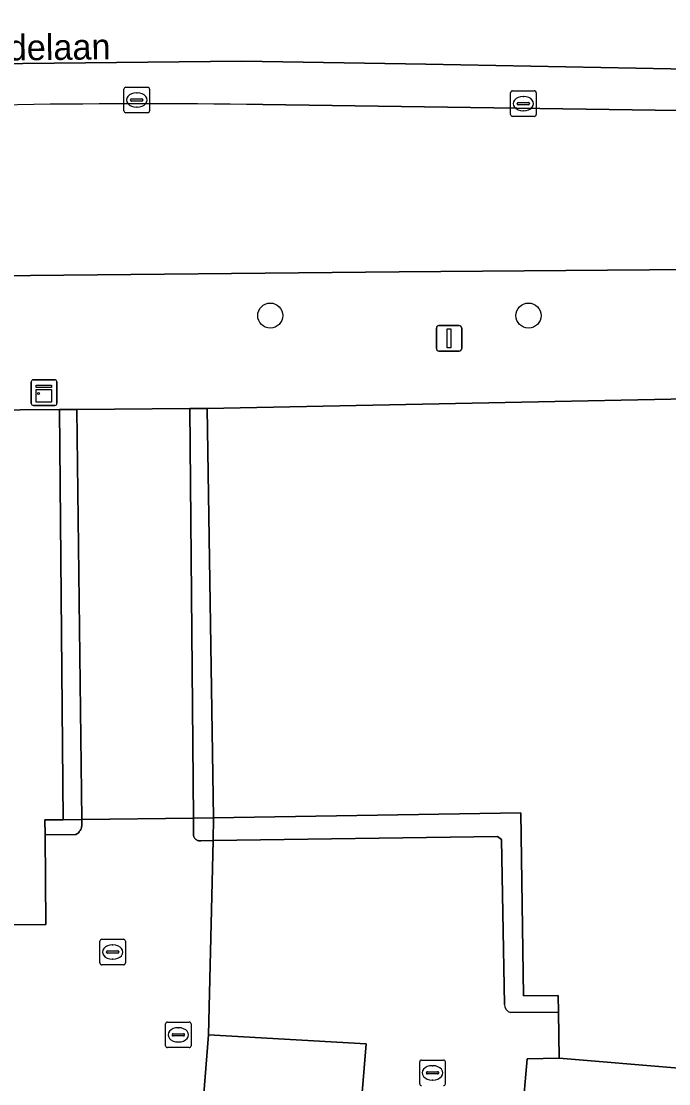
# Model space of a CAD drawing. Extents: x 160856 to 161310, y 384024 to 384878.
# Drawn here: x 161171.62 to 161196.94, y 384253.51 to 384295.05 of the extents above; entities that cross this region are included whole.
import ezdxf

# ---------------------------------------------------------------- set-up
doc = ezdxf.new("R2010")
doc.units = 0
for name, color, linetype in [('IMGEO_Boom', 7, 'Continuous'), ('IMGEO_Kast', 7, 'Continuous'), ('IMGEO_Kolk', 7, 'Continuous'), ('IMGEO_Lichtmast', 7, 'Continuous'), ('IMGEO_Openbare_ruimte_label', 7, 'Continuous'), ('IMGEO_Pand', 7, 'Continuous'), ('IMGEO_Pand_overbouw', 7, 'Continuous'), ('IMGEO_Parkeervlak_open', 7, 'Continuous'), ('IMGEO_Rijbaan_lokaal_gesloten', 7, 'Continuous'), ('IMGEO_Rijbaan_lokaal_open', 7, 'Continuous'), ('IMGEO_Rioolput', 7, 'Continuous'), ('IMGEO_Voetpad_open', 7, 'Continuous')]:
    doc.layers.add(name, color=color, linetype=linetype)

msp = doc.modelspace()

# ---------------------------------------------------------------- linework, layer by layer
at = {"layer": 'IMGEO_Boom'}
for centre in [(161181.357, 384283.546), (161191.456, 384283.546)]:
    msp.add_circle(centre, 0.489, dxfattribs=at)
at = {"layer": 'IMGEO_Kast'}
for p, q in [((161172.016, 384280.11), (161172.016, 384280.951)), ((161172.016, 384280.951), (161172.016, 384280.11)), ((161172.091, 384281.035), (161172.932, 384281.035)), ((161172.932, 384281.035), (161172.091, 384281.035)), ((161173.016, 384280.96), (161173.016, 384280.119)), ((161173.016, 384280.119), (161173.016, 384280.96)), ((161172.941, 384280.035), (161172.1, 384280.035)), ((161172.1, 384280.035), (161172.941, 384280.035))]:
    msp.add_line(p, q, dxfattribs=at)
for points in [[(161172.211, 384280.825), (161172.811, 384280.825), (161172.811, 384280.74), (161172.211, 384280.74), (161172.211, 384280.825)], [(161172.211, 384280.65), (161172.811, 384280.65), (161172.811, 384280.161), (161172.211, 384280.161), (161172.211, 384280.65)]]:
    msp.add_lwpolyline(points, dxfattribs=at)
msp.add_circle((161172.295, 384280.499), 0.0377, dxfattribs=at)
for centre, start, end in [((161172.094, 384280.957), 92.4484, 184.2845), ((161172.094, 384280.957), 92.4484, 184.2845), ((161172.938, 384280.957), 2.4484, 94.2845), ((161172.938, 384280.957), 2.4484, 94.2845), ((161172.094, 384280.113), 182.4484, 274.2845), ((161172.094, 384280.113), 182.4484, 274.2845), ((161172.938, 384280.113), 272.4484, 4.2845), ((161172.938, 384280.113), 272.4484, 4.2845)]:
    msp.add_arc(centre, 0.0779, start, end, dxfattribs=at)
at = {"layer": 'IMGEO_Kolk'}
for p, q in [((161175.64, 384291.548), (161175.64, 384292.4)), ((161175.715, 384292.474), (161176.567, 384292.474)), ((161176.641, 384292.4), (161176.641, 384291.548)), ((161175.899, 384291.968), (161175.899, 384291.98)), ((161175.942, 384292.017), (161176.34, 384292.017)), ((161176.128, 384292.254), (161176.153, 384292.254)), ((161176.383, 384291.98), (161176.383, 384291.968)), ((161190.755, 384291.407), (161190.755, 384292.259)), ((161190.83, 384292.333), (161191.682, 384292.333)), ((161191.243, 384292.113), (161191.268, 384292.113)), ((161191.756, 384292.259), (161191.756, 384291.407)), ((161176.337, 384291.931), (161175.939, 384291.931)), ((161176.151, 384291.694), (161176.126, 384291.694)), ((161191.014, 384291.827), (161191.014, 384291.839)), ((161191.452, 384291.79), (161191.054, 384291.79)), ((161191.057, 384291.876), (161191.455, 384291.876)), ((161191.266, 384291.553), (161191.241, 384291.553)), ((161191.498, 384291.839), (161191.498, 384291.827)), ((161176.567, 384291.474), (161175.715, 384291.474)), ((161191.682, 384291.333), (161190.83, 384291.333)), ((161177.265, 384254.998), (161177.265, 384255.85)), ((161177.34, 384255.924), (161178.192, 384255.924)), ((161178.266, 384255.85), (161178.266, 384254.998)), ((161177.524, 384255.418), (161177.524, 384255.43)), ((161177.567, 384255.467), (161177.965, 384255.467)), ((161177.753, 384255.704), (161177.778, 384255.704)), ((161178.008, 384255.43), (161178.008, 384255.418)), ((161177.962, 384255.381), (161177.564, 384255.381)), ((161177.776, 384255.144), (161177.751, 384255.144)), ((161178.192, 384254.924), (161177.34, 384254.924)), ((161187.203, 384253.512), (161187.203, 384254.364)), ((161187.278, 384254.438), (161188.13, 384254.438)), ((161187.691, 384254.218), (161187.716, 384254.218)), ((161188.204, 384254.364), (161188.204, 384253.512)), ((161187.462, 384253.932), (161187.462, 384253.944)), ((161187.9, 384253.895), (161187.502, 384253.895)), ((161187.505, 384253.981), (161187.903, 384253.981)), ((161187.946, 384253.944), (161187.946, 384253.932)), ((161187.714, 384253.658), (161187.689, 384253.658))]:
    msp.add_line(p, q, dxfattribs=at)
for points in [[(161175.64, 384291.548), (161175.64, 384292.4)], [(161175.715, 384292.474), (161176.567, 384292.474)], [(161176.641, 384292.4), (161176.641, 384291.548)], [(161190.755, 384291.407), (161190.755, 384292.259)], [(161190.83, 384292.333), (161191.682, 384292.333)], [(161191.756, 384292.259), (161191.756, 384291.407)], [(161176.567, 384291.474), (161175.715, 384291.474)], [(161191.682, 384291.333), (161190.83, 384291.333)], [(161177.265, 384254.998), (161177.265, 384255.85)], [(161177.34, 384255.924), (161178.192, 384255.924)], [(161178.266, 384255.85), (161178.266, 384254.998)], [(161178.192, 384254.924), (161177.34, 384254.924)], [(161187.203, 384253.512), (161187.203, 384254.364)], [(161187.278, 384254.438), (161188.13, 384254.438)], [(161188.204, 384254.364), (161188.204, 384253.512)]]:
    msp.add_lwpolyline(points, dxfattribs=at)
for centre, radius, start, end in [((161175.717, 384292.398), 0.0765, 91.552, 178.448), ((161175.717, 384292.398), 0.0765, 91.552, 178.448), ((161176.565, 384292.398), 0.0765, 1.552, 88.448), ((161176.565, 384292.398), 0.0765, 1.552, 88.448), ((161175.939, 384291.977), 0.0403, 85.8775, 175.7526), ((161175.936, 384291.967), 0.0366, 178.938, 274.7102), ((161176.34, 384291.974), 0.043, 264.8664, 352.4533), ((161176.344, 384291.979), 0.0386, 1.7309, 96.639), ((161190.832, 384292.257), 0.0765, 91.552, 178.448), ((161190.832, 384292.257), 0.0765, 91.552, 178.448), ((161191.68, 384292.257), 0.0765, 1.552, 88.448), ((161191.68, 384292.257), 0.0765, 1.552, 88.448), ((161175.717, 384291.55), 0.0765, 181.552, 268.448), ((161175.717, 384291.55), 0.0765, 181.552, 268.448), ((161176.565, 384291.55), 0.0765, 271.552, 358.448), ((161176.565, 384291.55), 0.0765, 271.552, 358.448), ((161191.054, 384291.836), 0.0403, 85.8775, 175.7526), ((161191.051, 384291.826), 0.0366, 178.938, 274.7102), ((161191.455, 384291.833), 0.043, 264.8664, 352.4533), ((161191.459, 384291.838), 0.0386, 1.7309, 96.639), ((161190.832, 384291.409), 0.0765, 181.552, 268.448), ((161190.832, 384291.409), 0.0765, 181.552, 268.448), ((161191.68, 384291.409), 0.0765, 271.552, 358.448), ((161191.68, 384291.409), 0.0765, 271.552, 358.448), ((161177.342, 384255.848), 0.0765, 91.552, 178.448), ((161177.342, 384255.848), 0.0765, 91.552, 178.448), ((161178.19, 384255.848), 0.0765, 1.552, 88.448), ((161178.19, 384255.848), 0.0765, 1.552, 88.448), ((161177.564, 384255.427), 0.0403, 85.8775, 175.7526), ((161177.561, 384255.417), 0.0366, 178.938, 274.7102), ((161177.965, 384255.424), 0.043, 264.8664, 352.4533), ((161177.969, 384255.429), 0.0386, 1.7309, 96.639), ((161177.342, 384255), 0.0765, 181.552, 268.448), ((161177.342, 384255), 0.0765, 181.552, 268.448), ((161178.19, 384255), 0.0765, 271.552, 358.448), ((161178.19, 384255), 0.0765, 271.552, 358.448), ((161187.28, 384254.362), 0.0765, 91.552, 178.448), ((161187.28, 384254.362), 0.0765, 91.552, 178.448), ((161188.128, 384254.362), 0.0765, 1.552, 88.448), ((161188.128, 384254.362), 0.0765, 1.552, 88.448), ((161187.502, 384253.941), 0.0403, 85.8775, 175.7526), ((161187.499, 384253.931), 0.0366, 178.938, 274.7102), ((161187.903, 384253.938), 0.043, 264.8664, 352.4533), ((161187.907, 384253.943), 0.0386, 1.7309, 96.639), ((161187.28, 384253.514), 0.0765, 181.552, 268.448), ((161187.28, 384253.514), 0.0765, 181.552, 268.448), ((161188.128, 384253.514), 0.0765, 271.552, 358.448), ((161188.128, 384253.514), 0.0765, 271.552, 358.448)]:
    msp.add_arc(centre, radius, start, end, dxfattribs=at)
for centre, major_axis, ratio, start_param, end_param in [((161176.127, 384291.974), (-0.387, 0.002), 0.722429, 4.712389, 7.853982), ((161176.152, 384291.974), (-0.39, 0.002), 0.717154, 1.570796, 4.712389), ((161191.242, 384291.833), (-0.387, 0.002), 0.722429, 4.712389, 7.853982), ((161191.267, 384291.833), (-0.39, 0.002), 0.717154, 1.570796, 4.712389), ((161177.752, 384255.424), (-0.387, 0.002), 0.722429, 4.712389, 7.853982), ((161177.777, 384255.424), (-0.39, 0.002), 0.717154, 1.570796, 4.712389), ((161187.69, 384253.938), (-0.387, 0.002), 0.722429, 4.712389, 7.853982), ((161187.715, 384253.938), (-0.39, 0.002), 0.717154, 1.570796, 4.712389)]:
    msp.add_ellipse(centre, major_axis=major_axis, ratio=ratio, start_param=start_param, end_param=end_param, dxfattribs=at)
at = {"layer": 'IMGEO_Lichtmast'}
for p, q in [((161187.855, 384282.257), (161187.855, 384283.057)), ((161187.855, 384283.057), (161187.855, 384282.257)), ((161187.955, 384283.157), (161188.745, 384283.157)), ((161188.745, 384283.157), (161187.955, 384283.157)), ((161188.845, 384283.057), (161188.845, 384282.257)), ((161188.845, 384282.257), (161188.845, 384283.057)), ((161188.745, 384282.157), (161187.955, 384282.157)), ((161187.955, 384282.157), (161188.745, 384282.157))]:
    msp.add_line(p, q, dxfattribs=at)
msp.add_lwpolyline([(161188.275, 384283.032), (161188.425, 384283.032), (161188.425, 384282.282), (161188.275, 384282.282), (161188.275, 384283.032)], dxfattribs=at)
for centre, start, end in [((161187.955, 384283.057), 90, 180), ((161187.955, 384283.057), 90, 180), ((161188.745, 384283.057), 0, 90), ((161188.745, 384283.057), 360, 90), ((161187.955, 384282.257), 180, 270), ((161187.955, 384282.257), 180, 270), ((161188.745, 384282.257), 270, 0), ((161188.745, 384282.257), 270, 0)]:
    msp.add_arc(centre, 0.1, start, end, dxfattribs=at)
at = {"layer": 'IMGEO_Pand'}
for points in [[(161205.02, 384274.053), (161204.963, 384277.713), (161204.063, 384277.698), (161201.671, 384280.086), (161199.622, 384280.025), (161199.613, 384280.328), (161178.89, 384279.915), (161179.141, 384263.912), (161191.154, 384264.1), (161191.266, 384256.946), (161192.617, 384256.967), (161192.627, 384256.305), (161192.655, 384254.508), (161202.014, 384253.733), (161202.369, 384259.581), (161204.63, 384259.631), (161205.289, 384259.645), (161205.145, 384265.777)], [(161173.123, 384279.875), (161165.444, 384279.809), (161165.617, 384259.684), (161170.142, 384259.723), (161172.586, 384259.744), (161172.556, 384263.247), (161172.551, 384263.828), (161173.26, 384263.834)]]:
    msp.add_lwpolyline(points, close=True, dxfattribs=at)
for points in [[(161184.694, 384250), (161185.112, 384255.077), (161178.951, 384255.419), (161178.514, 384250)], [(161205.595, 384253.449), (161204.244, 384253.556), (161202.014, 384253.733), (161192.655, 384254.508), (161191.41, 384254.489), (161191.007, 384250)]]:
    msp.add_lwpolyline(points, dxfattribs=at)
at = {"layer": 'IMGEO_Pand_overbouw'}
msp.add_lwpolyline([(161179.141, 384263.912), (161178.89, 384279.915), (161178.21, 384279.91), (161173.791, 384279.88), (161173.123, 384279.875), (161173.26, 384263.834), (161173.988, 384263.844), (161178.359, 384263.902)], close=True, dxfattribs=at)
at = {"layer": 'IMGEO_Parkeervlak_open'}
for points in [[(161200.882, 384291.443), (161198.218, 384291.55), (161181.07, 384291.795)], [(161160.607, 384291.455), (161150.667, 384291.117), (161154.932, 384284.943), (161186.405, 384285.262), (161204.336, 384285.396), (161200.882, 384291.443)]]:
    msp.add_lwpolyline(points, dxfattribs=at)
msp.add_arc((161176.485, 383951.818), 340.008, 89.22726, 92.67654, dxfattribs=at)
at = {"layer": 'IMGEO_Rijbaan_lokaal_gesloten'}
for points in [[(161149.536, 384295.795), (161145.782, 384295.515), (161145.919, 384292.623), (161158.076, 384293.055), (161169.217, 384293.379), (161180.249, 384293.487), (161187.445, 384293.379), (161201.12, 384293.117), (161202.291, 384293.04), (161203.531, 384292.747), (161204.748, 384292.285), (161205.642, 384291.869), (161207.3, 384290.939), (161209.234, 384290.779), (161210.728, 384290.663), (161210.816, 384290.656), (161213.716, 384290.433), (161213.842, 384299.034)], [(161202.115, 384291.369), (161207.3, 384290.939), (161205.642, 384291.869), (161204.748, 384292.285), (161203.531, 384292.747), (161202.291, 384293.04), (161201.12, 384293.117), (161187.445, 384293.379), (161180.249, 384293.487), (161169.217, 384293.379), (161158.076, 384293.055), (161145.919, 384292.623)], [(161181.07, 384291.795), (161198.218, 384291.55), (161200.882, 384291.443), (161201.743, 384291.409)]]:
    msp.add_lwpolyline(points, dxfattribs=at)
msp.add_arc((161176.485, 383951.818), 340.008, 89.22726, 92.67654, dxfattribs=at)
at = {"layer": 'IMGEO_Rijbaan_lokaal_open'}
msp.add_lwpolyline([(161178.21, 384279.91), (161173.791, 384279.88), (161173.988, 384263.844), (161178.359, 384263.902)], close=True, dxfattribs=at)
for points in [[(161178.514, 384250), (161178.951, 384255.419), (161179.121, 384263.018), (161178.646, 384263.011), (161178.624, 384263.008), (161178.602, 384263.008), (161178.58, 384263.009), (161178.558, 384263.013), (161178.536, 384263.018), (161178.515, 384263.025), (161178.495, 384263.034), (161178.476, 384263.045), (161178.457, 384263.058), (161178.44, 384263.072), (161178.424, 384263.088), (161178.41, 384263.105), (161178.397, 384263.123), (161178.386, 384263.142), (161178.377, 384263.163), (161178.37, 384263.183), (161178.364, 384263.205), (161178.359, 384263.902), (161173.988, 384263.844), (161173.99, 384263.654), (161173.99, 384263.639), (161173.989, 384263.6), (161173.983, 384263.562), (161173.975, 384263.524), (161173.963, 384263.487), (161173.948, 384263.452), (161173.929, 384263.418), (161173.908, 384263.385), (161173.884, 384263.355), (161173.857, 384263.327), (161173.828, 384263.302), (161173.797, 384263.279), (161173.764, 384263.259), (161172.556, 384263.247), (161172.586, 384259.744), (161170.142, 384259.723)], [(161190.521, 384256.61), (161190.395, 384263.065), (161190.248, 384263.18), (161179.121, 384263.018), (161178.951, 384255.419), (161185.112, 384255.077), (161184.694, 384250), (161184.554, 384248.305), (161190.811, 384247.814), (161191.007, 384250), (161191.41, 384254.489), (161192.655, 384254.508), (161192.627, 384256.305), (161190.752, 384256.294)]]:
    msp.add_lwpolyline(points, dxfattribs=at)
msp.add_arc((161190.838, 384256.599), 0.317, 178.0555, 254.279, dxfattribs=at)
at = {"layer": 'IMGEO_Rioolput'}
for p, q in [((161174.772, 384259.161), (161175.624, 384259.161)), ((161174.697, 384258.235), (161174.697, 384259.087)), ((161175.185, 384258.941), (161175.21, 384258.941)), ((161175.698, 384259.087), (161175.698, 384258.235)), ((161174.956, 384258.655), (161174.956, 384258.667)), ((161175.394, 384258.618), (161174.996, 384258.618)), ((161174.999, 384258.704), (161175.397, 384258.704)), ((161175.208, 384258.381), (161175.183, 384258.381)), ((161175.44, 384258.667), (161175.44, 384258.655)), ((161175.624, 384258.161), (161174.772, 384258.161))]:
    msp.add_line(p, q, dxfattribs=at)
for points in [[(161174.772, 384259.161), (161175.624, 384259.161)], [(161174.697, 384258.235), (161174.697, 384259.087)], [(161175.698, 384259.087), (161175.698, 384258.235)], [(161175.624, 384258.161), (161174.772, 384258.161)]]:
    msp.add_lwpolyline(points, dxfattribs=at)
for centre, radius, start, end in [((161174.774, 384259.085), 0.0765, 91.552, 178.448), ((161174.774, 384259.085), 0.0765, 91.552, 178.448), ((161175.622, 384259.085), 0.0765, 1.552, 88.448), ((161175.622, 384259.085), 0.0765, 1.552, 88.448), ((161174.996, 384258.664), 0.0403, 85.8775, 175.7526), ((161174.993, 384258.654), 0.0366, 178.938, 274.7102), ((161175.397, 384258.661), 0.043, 264.8664, 352.4533), ((161175.401, 384258.666), 0.0386, 1.7309, 96.639), ((161174.774, 384258.237), 0.0765, 181.552, 268.448), ((161174.774, 384258.237), 0.0765, 181.552, 268.448), ((161175.622, 384258.237), 0.0765, 271.552, 358.448), ((161175.622, 384258.237), 0.0765, 271.552, 358.448)]:
    msp.add_arc(centre, radius, start, end, dxfattribs=at)
for centre, major_axis, ratio, start_param, end_param in [((161175.184, 384258.661), (-0.387, 0.002), 0.722429, 4.712389, 7.853982), ((161175.209, 384258.661), (-0.39, 0.002), 0.717154, 1.570796, 4.712389)]:
    msp.add_ellipse(centre, major_axis=major_axis, ratio=ratio, start_param=start_param, end_param=end_param, dxfattribs=at)
at = {"layer": 'IMGEO_Voetpad_open'}
for points in [[(161201.743, 384291.409), (161200.882, 384291.443), (161204.336, 384285.396), (161186.405, 384285.262), (161154.932, 384284.943), (161150.667, 384291.117), (161145.998, 384290.958)], [(161165.444, 384279.809), (161173.123, 384279.875), (161173.791, 384279.88), (161178.21, 384279.91), (161178.89, 384279.915), (161199.613, 384280.328), (161201.86, 384280.373), (161204.911, 384280.464), (161209.303, 384280.318), (161213.412, 384280.458), (161213.499, 384281.408), (161213.64, 384282.954)], [(161190.752, 384256.294), (161192.627, 384256.305), (161192.617, 384256.967), (161191.266, 384256.946), (161191.154, 384264.1), (161179.141, 384263.912), (161179.121, 384263.018), (161190.248, 384263.18), (161190.395, 384263.065), (161190.521, 384256.61)]]:
    msp.add_lwpolyline(points, dxfattribs=at)
for points in [[(161179.141, 384263.912), (161178.89, 384279.915), (161178.21, 384279.91), (161178.359, 384263.902)], [(161173.988, 384263.844), (161173.791, 384279.88), (161173.123, 384279.875), (161173.26, 384263.834)], [(161173.764, 384263.259), (161173.797, 384263.279), (161173.828, 384263.302), (161173.857, 384263.327), (161173.884, 384263.355), (161173.908, 384263.385), (161173.929, 384263.418), (161173.948, 384263.452), (161173.963, 384263.487), (161173.975, 384263.524), (161173.983, 384263.562), (161173.989, 384263.6), (161173.99, 384263.639), (161173.99, 384263.654), (161173.988, 384263.844), (161173.26, 384263.834), (161172.551, 384263.828), (161172.556, 384263.247)], [(161179.141, 384263.912), (161178.359, 384263.902), (161178.364, 384263.205), (161178.37, 384263.183), (161178.377, 384263.163), (161178.386, 384263.142), (161178.397, 384263.123), (161178.41, 384263.105), (161178.424, 384263.088), (161178.44, 384263.072), (161178.457, 384263.058), (161178.476, 384263.045), (161178.495, 384263.034), (161178.515, 384263.025), (161178.536, 384263.018), (161178.558, 384263.013), (161178.58, 384263.009), (161178.602, 384263.008), (161178.624, 384263.008), (161178.646, 384263.011), (161179.121, 384263.018)]]:
    msp.add_lwpolyline(points, close=True, dxfattribs=at)
msp.add_arc((161190.838, 384256.599), 0.317, 178.0555, 254.279, dxfattribs=at)

# ---------------------------------------------------------------- texts
at = {"layer": 'IMGEO_Openbare_ruimte_label'}
msp.add_text('Gildelaan', height=1, rotation=0.6875, dxfattribs=at).set_placement((161169.469, 384293.499))

doc.saveas('drawing.dxf')
